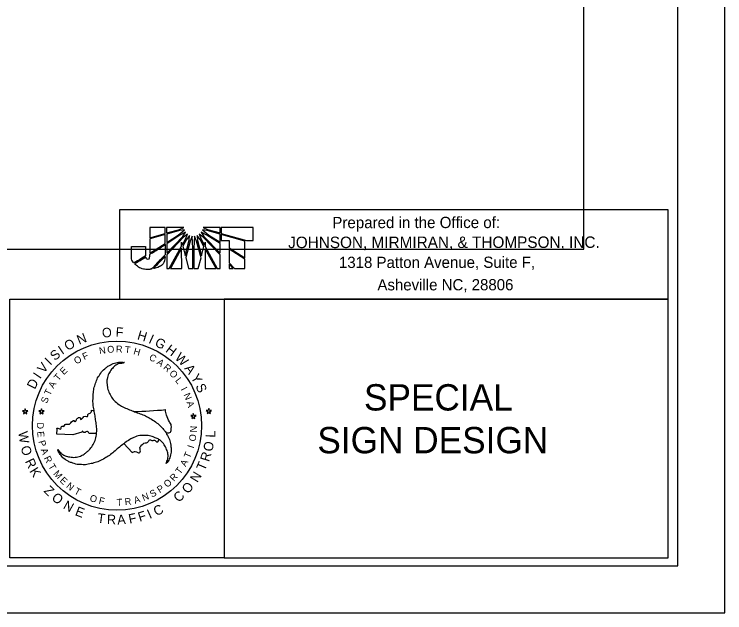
# Model space of a CAD drawing. Extents: x 766449 to 768137, y 650958 to 652521.
# Drawn here: x 767759.5 to 768137.3, y 651421.3 to 651739.5 of the extents above; entities that cross this region are included whole.
import ezdxf

# ---------------------------------------------------------------- set-up
doc = ezdxf.new("R2010")
doc.units = 0
for name, color, linetype in [('Default', 7, 'Continuous'), ('DEV BORDER CELL', 7, 'Continuous'), ('DEV DOT SWIRL SEAL CELL', 7, 'Continuous'), ('Scratch_Level_0', 7, 'Continuous'), ('Sheet Plan CELL', 7, 'Continuous'), ('Sheet Plot Border Outside CELL', 7, 'Continuous'), ('Sheet Title CELL', 7, 'Continuous'), ('Text', 7, 'Continuous')]:
    doc.layers.add(name, color=color, linetype=linetype)

msp = doc.modelspace()

# ---------------------------------------------------------------- linework, layer by layer
at = {"layer": 'Default'}
for p, q in [((767839.76, 651626.07), (767831.66, 651626.07)), ((767831.66, 651626.07), (767831.67, 651620.69)), ((767831.67, 651620.69), (767839.76, 651622.95)), ((767839.76, 651622.95), (767839.76, 651626.07)), ((767849.71, 651626.12), (767840.6, 651626.11)), ((767840.6, 651626.11), (767840.6, 651623.21)), ((767840.6, 651623.21), (767847.39, 651625.09)), ((767847.39, 651624.46), (767840.61, 651622.59)), ((767846.68, 651622.06), (767850.04, 651624.79)), ((767847.39, 651625.09), (767849.71, 651626.12)), ((767850.04, 651624.79), (767847.39, 651624.46)), ((767850.7, 651623.53), (767847.62, 651621.96)), ((767849.14, 651621.34), (767850.7, 651623.53)), ((767858.87, 651623.54), (767860.43, 651621.31)), ((767862, 651621.98), (767858.87, 651623.54)), ((767859.58, 651624.79), (767862.97, 651622.02)), ((767862.07, 651624.48), (767859.58, 651624.79)), ((767869.01, 651626.1), (767860.03, 651626.13)), ((767860.03, 651626.13), (767862.3, 651625.06)), ((767869.01, 651622.57), (767862.07, 651624.48)), ((767862.3, 651625.06), (767869.01, 651623.19)), ((767869.01, 651623.19), (767869.01, 651626.1)), ((767886.65, 651626.15), (767869.63, 651626.14)), ((767869.63, 651626.14), (767869.64, 651623.01)), ((767869.64, 651623.01), (767869.64, 651622.92)), ((767869.64, 651622.92), (767883.04, 651619.18)), ((767886.66, 651619.18), (767886.65, 651626.15)), ((767839.76, 651622.36), (767831.67, 651620.08)), ((767831.67, 651620.08), (767831.68, 651612.53)), ((767839.77, 651617.67), (767839.76, 651622.36)), ((767840.61, 651622.59), (767840.61, 651618.2)), ((767840.61, 651618.2), (767846.68, 651622.06)), ((767847.62, 651621.96), (767840.61, 651617.5)), ((767840.61, 651612.45), (767849.14, 651621.34)), ((767849.49, 651620.9), (767840.62, 651611.59)), ((767848.96, 651616.88), (767850.65, 651619.96)), ((767851.2, 651619.78), (767849.19, 651616.11)), ((767851.64, 651622.56), (767849.49, 651620.9)), ((767850.49, 651611.25), (767852.58, 651619.34)), ((767850.65, 651619.96), (767851.64, 651622.56)), ((767853.03, 651618.88), (767850.76, 651610.13)), ((767852.8, 651621.84), (767851.2, 651619.78)), ((767852.58, 651619.34), (767852.8, 651621.84)), ((767854.14, 651621.48), (767853.03, 651618.88)), ((767854.49, 651615.09), (767854.14, 651621.48)), ((767855.48, 651621.48), (767855.07, 651615.09)), ((767856.55, 651618.89), (767855.48, 651621.48)), ((767858.88, 651610), (767856.55, 651618.89)), ((767856.77, 651621.84), (767857.04, 651619.25)), ((767858.34, 651619.78), (767856.77, 651621.84)), ((767857.04, 651619.25), (767859.15, 651611.07)), ((767857.92, 651622.56), (767858.91, 651619.97)), ((767860.07, 651620.91), (767857.92, 651622.56)), ((767860.44, 651615.99), (767858.34, 651619.78)), ((767858.91, 651619.97), (767860.65, 651616.75)), ((767868.97, 651611.54), (767860.07, 651620.91)), ((767860.43, 651621.31), (767868.96, 651612.38)), ((767868.96, 651617.56), (767862, 651621.98)), ((767862.97, 651622.02), (767868.96, 651618.28)), ((767868.96, 651618.28), (767869.01, 651622.57)), ((767869.64, 651622.44), (767869.64, 651622.39)), ((767882.19, 651618.87), (767869.64, 651622.44)), ((767869.64, 651622.39), (767869.64, 651619.13)), ((767869.64, 651619.13), (767873.8, 651619.13)), ((767873.8, 651619.13), (767873.8, 651615.24)), ((767882.19, 651609.93), (767882.19, 651618.87)), ((767883.04, 651619.18), (767886.66, 651619.18)), ((767831.68, 651612.53), (767839.77, 651617.67)), ((767840.61, 651617.5), (767840.61, 651612.45)), ((767841.96, 651604.24), (767848.56, 651616.21)), ((767848.56, 651616.21), (767848.56, 651618.35)), ((767848.56, 651618.35), (767848.96, 651616.88)), ((767849.19, 651616.11), (767850.49, 651611.25)), ((767854.5, 651604.3), (767854.49, 651615.09)), ((767855.07, 651615.09), (767855.08, 651604.3)), ((767859.15, 651611.07), (767860.44, 651615.99)), ((767860.65, 651616.75), (767861.06, 651618.36)), ((767861.06, 651618.36), (767861.07, 651615.99)), ((767861.07, 651615.99), (767867.54, 651604.27)), ((767868.96, 651612.38), (767868.96, 651617.56)), ((767873.8, 651615.24), (767882.19, 651609.93)), ((767840.62, 651611.59), (767840.62, 651604.24)), ((767848.56, 651615.05), (767842.59, 651604.24)), ((767848.62, 651604.25), (767848.56, 651615.05)), ((767866.87, 651604.31), (767861.07, 651614.83)), ((767861.07, 651614.83), (767861.08, 651604.3)), ((767868.97, 651604.27), (767868.97, 651611.54)), ((767873.8, 651614.57), (767873.81, 651607.33)), ((767882.19, 651609.3), (767873.8, 651614.57)), ((767850.76, 651610.13), (767852.29, 651604.29)), ((767857.32, 651604.3), (767858.88, 651610)), ((767882.2, 651604.28), (767882.19, 651609.3)), ((767840.62, 651604.24), (767841.96, 651604.24)), ((767842.59, 651604.24), (767848.62, 651604.25)), ((767852.29, 651604.29), (767854.5, 651604.3)), ((767855.08, 651604.3), (767857.32, 651604.3)), ((767861.08, 651604.3), (767866.87, 651604.31)), ((767867.54, 651604.27), (767868.97, 651604.27)), ((767873.81, 651607.33), (767876.71, 651604.28)), ((767875.91, 651604.27), (767873.81, 651606.54)), ((767873.81, 651606.54), (767873.81, 651604.27)), ((767873.81, 651604.27), (767875.91, 651604.27)), ((767876.71, 651604.28), (767882.2, 651604.28))]:
    msp.add_line(p, q, dxfattribs=at)
for points in [[(767831.67, 651620.69), (767839.76, 651622.95), (767839.76, 651626.07), (767831.66, 651626.07), (767831.67, 651620.69)], [(767847.39, 651625.09), (767849.71, 651626.12), (767840.6, 651626.11), (767840.6, 651623.21), (767847.39, 651625.09)], [(767840.61, 651622.59), (767840.61, 651618.2), (767846.68, 651622.06), (767850.04, 651624.79), (767847.39, 651624.46), (767840.61, 651622.59)], [(767840.61, 651617.5), (767840.61, 651612.45), (767849.14, 651621.34), (767850.7, 651623.53), (767847.62, 651621.96), (767840.61, 651617.5)], [(767858.87, 651623.54), (767860.43, 651621.31), (767868.96, 651612.38), (767868.96, 651617.56), (767862, 651621.98), (767858.87, 651623.54)], [(767859.58, 651624.79), (767862.97, 651622.02), (767868.96, 651618.28), (767869.01, 651622.57), (767862.07, 651624.48), (767859.58, 651624.79)], [(767862.3, 651625.06), (767869.01, 651623.19), (767869.01, 651626.1), (767860.03, 651626.13), (767862.3, 651625.06)], [(767831.68, 651612.53), (767839.77, 651617.67), (767839.76, 651622.36), (767831.67, 651620.08), (767831.68, 651612.53)], [(767851.64, 651622.56), (767849.49, 651620.9), (767840.62, 651611.59), (767840.62, 651604.24), (767841.96, 651604.24), (767848.56, 651616.21), (767848.56, 651618.35), (767848.96, 651616.88), (767850.65, 651619.96), (767851.64, 651622.56)], [(767852.8, 651621.84), (767851.2, 651619.78), (767849.19, 651616.11), (767850.49, 651611.25), (767852.58, 651619.34), (767852.8, 651621.84)], [(767853.03, 651618.88), (767850.76, 651610.13), (767852.29, 651604.29), (767854.5, 651604.3), (767854.49, 651615.09), (767854.14, 651621.48), (767853.03, 651618.88)], [(767855.48, 651621.48), (767855.07, 651615.09), (767855.08, 651604.3), (767857.32, 651604.3), (767858.88, 651610), (767856.55, 651618.89), (767855.48, 651621.48)], [(767856.77, 651621.84), (767857.04, 651619.25), (767859.15, 651611.07), (767860.44, 651615.99), (767858.34, 651619.78), (767856.77, 651621.84)], [(767857.92, 651622.56), (767858.91, 651619.97), (767860.65, 651616.75), (767861.06, 651618.36), (767861.07, 651615.99), (767867.54, 651604.27), (767868.97, 651604.27), (767868.97, 651611.54), (767860.07, 651620.91), (767857.92, 651622.56)], [(767869.64, 651622.44), (767869.64, 651622.39), (767869.64, 651619.13), (767873.8, 651619.13), (767873.8, 651615.24), (767882.19, 651609.93), (767882.19, 651618.87), (767869.64, 651622.44)], [(767842.59, 651604.24), (767848.62, 651604.25), (767848.56, 651615.05), (767842.59, 651604.24)], [(767861.08, 651604.3), (767866.87, 651604.31), (767861.07, 651614.83), (767861.08, 651604.3)], [(767873.8, 651614.57), (767873.81, 651607.33), (767876.71, 651604.28), (767882.2, 651604.28), (767882.19, 651609.3), (767873.8, 651614.57), (767873.8, 651614.57)], [(767873.81, 651604.27), (767873.81, 651604.27), (767875.91, 651604.27), (767873.81, 651606.54), (767873.81, 651604.27)]]:
    msp.add_lwpolyline(points, dxfattribs=at)
for points in [[(767829.35, 651616), (767829.35, 651616), (767821.85, 651616), (767821.85, 651616), (767821.85, 651616), (767821.86, 651611.31), (767821.86, 651611.31), (767821.86, 651611.31), (767821.86, 651610.81), (767821.86, 651610.81), (767821.86, 651609.34), (767822.34, 651608.18), (767823.2, 651607.21), (767823.2, 651607.21), (767829.35, 651610.95), (767829.35, 651611.05), (767829.35, 651611.05), (767829.35, 651616), (767829.35, 651616)], [(767829.35, 651616), (767829.35, 651616), (767821.85, 651616), (767821.85, 651616), (767821.85, 651616), (767821.86, 651611.31), (767821.86, 651611.31), (767821.86, 651611.31), (767821.86, 651610.81), (767821.86, 651610.81), (767821.86, 651609.34), (767822.34, 651608.18), (767823.2, 651607.21), (767823.2, 651607.21), (767829.35, 651610.95), (767829.35, 651611.05), (767829.35, 651611.05), (767829.35, 651616), (767829.35, 651616)], [(767830.52, 651609.26), (767830.04, 651609.26), (767829.62, 651609.52), (767829.45, 651610.42), (767829.45, 651610.42), (767823.64, 651606.82), (767823.64, 651606.82), (767825.43, 651604.94), (767828.29, 651603.82), (767830.71, 651603.82), (767831.34, 651603.82), (767831.82, 651603.87), (767832.49, 651604.01), (767832.49, 651604.01), (767839.77, 651611.55), (767839.77, 651611.55), (767839.77, 651611.55), (767839.77, 651617), (767839.77, 651617), (767839.77, 651617), (767831.68, 651611.85), (767831.68, 651611.85), (767831.68, 651609.81), (767831.18, 651609.26), (767830.52, 651609.26)], [(767830.52, 651609.26), (767830.04, 651609.26), (767829.62, 651609.52), (767829.45, 651610.42), (767829.45, 651610.42), (767823.64, 651606.82), (767823.64, 651606.82), (767825.43, 651604.94), (767828.29, 651603.82), (767830.71, 651603.82), (767831.34, 651603.82), (767831.82, 651603.87), (767832.49, 651604.01), (767832.49, 651604.01), (767839.77, 651611.55), (767839.77, 651611.55), (767839.77, 651611.55), (767839.77, 651617), (767839.77, 651617), (767839.77, 651617), (767831.68, 651611.85), (767831.68, 651611.85), (767831.68, 651609.81), (767831.18, 651609.26), (767830.52, 651609.26)], [(767839.77, 651610.7), (767839.77, 651610.7), (767833.47, 651604.18), (767833.47, 651604.18), (767836.56, 651604.95), (767839.63, 651606.99), (767839.77, 651610.7)], [(767839.77, 651610.7), (767839.77, 651610.7), (767833.47, 651604.18), (767833.47, 651604.18), (767836.56, 651604.95), (767839.63, 651606.99), (767839.77, 651610.7)]]:
    msp.add_open_spline(points, degree=3, dxfattribs=at)
at = {"layer": 'DEV BORDER CELL'}
for points in [[(768112.34, 652496.28), (766612.34, 652496.28), (766612.34, 651446.28), (768112.34, 651446.28)], [(767757.19, 651588.05), (767871.19, 651588.05), (767871.19, 651450.55), (767757.19, 651450.55)], [(768107.19, 651588.05), (767871.19, 651588.05), (767871.19, 651450.55), (768107.19, 651450.55)]]:
    msp.add_lwpolyline(points, close=True, dxfattribs=at)
at = {"layer": 'DEV DOT SWIRL SEAL CELL'}
for p, q in [((767763.92, 651528.71), (767764.8, 651528.07)), ((767765, 651528.71), (767763.92, 651528.71)), ((767765.32, 651529.72), (767765, 651528.71)), ((767765.68, 651528.71), (767765.32, 651529.72)), ((767766.77, 651528.71), (767765.68, 651528.71)), ((767765.89, 651528.07), (767766.77, 651528.71)), ((767765.89, 651528.07), (767766.77, 651528.71)), ((767773.68, 651528.7), (767772.6, 651528.7)), ((767772.6, 651528.7), (767773.48, 651528.06)), ((767774, 651529.7), (767773.68, 651528.7)), ((767774.36, 651528.7), (767774, 651529.7)), ((767775.45, 651528.7), (767774.36, 651528.7)), ((767774.56, 651528.06), (767775.45, 651528.7)), ((767862.73, 651528.85), (767861.64, 651528.85)), ((767861.64, 651528.85), (767862.53, 651528.21)), ((767862.53, 651528.21), (767862.2, 651527.17)), ((767863.05, 651529.86), (767862.73, 651528.85)), ((767863.41, 651528.85), (767863.05, 651529.86)), ((767864.49, 651528.85), (767863.41, 651528.85)), ((767863.61, 651528.21), (767864.49, 651528.85)), ((767863.93, 651527.17), (767863.61, 651528.21)), ((767764.8, 651528.07), (767764.48, 651527.03)), ((767764.48, 651527.03), (767765.32, 651527.67)), ((767765.32, 651527.67), (767766.21, 651527.03)), ((767765.32, 651527.67), (767766.21, 651527.03)), ((767766.21, 651527.03), (767765.89, 651528.07)), ((767766.21, 651527.03), (767765.89, 651528.07)), ((767773.48, 651528.06), (767773.16, 651527.01)), ((767773.16, 651527.01), (767774, 651527.66)), ((767774, 651527.66), (767774.89, 651527.01)), ((767774.89, 651527.01), (767774.56, 651528.06)), ((767854.45, 651526.21), (767853.37, 651526.21)), ((767853.37, 651526.21), (767854.25, 651525.57)), ((767854.25, 651525.57), (767853.93, 651524.53)), ((767853.93, 651524.53), (767854.77, 651525.17)), ((767854.77, 651527.21), (767854.45, 651526.21)), ((767855.13, 651526.21), (767854.77, 651527.21)), ((767854.77, 651525.17), (767855.65, 651524.53)), ((767856.22, 651526.21), (767855.13, 651526.21)), ((767855.33, 651525.57), (767856.22, 651526.21)), ((767855.65, 651524.53), (767855.33, 651525.57)), ((767862.2, 651527.17), (767863.05, 651527.81)), ((767863.05, 651527.81), (767863.93, 651527.17)), ((767782.25, 651516.27), (767782.33, 651518.92)), ((767795.44, 651517.37), (767790.64, 651515.96)), ((767790.64, 651515.96), (767782.25, 651516.27)), ((767799.14, 651516.81), (767803.36, 651516.77)), ((767817.89, 651511.19), (767822.2, 651506.52))]:
    msp.add_line(p, q, dxfattribs=at)
for start, end in [(265.6785, 265.9762), (271.2035, 275.3236)]:
    msp.add_arc((767818.28, 651761.45), 233.19, start, end, dxfattribs=at)
for points in [[(767782.66, 651508.16), (767784.4, 651506.14), (767786.58, 651504.75), (767789.07, 651504.1), (767791.89, 651503.94), (767794.76, 651504.61), (767796.67, 651505.58), (767797.47, 651506.22), (767798.87, 651507.33), (767799.86, 651508.4), (767801.53, 651510.76), (767802.82, 651513.55), (767803.35, 651516.75), (767803.38, 651517.02), (767803.35, 651520.02), (767802.95, 651523.06), (767802.52, 651525.98), (767801.98, 651529.01), (767801.5, 651532.02), (767801.45, 651534.95), (767801.64, 651538.3), (767802.12, 651541.18), (767803.06, 651544.13), (767803.57, 651545.53), (767804.27, 651546.65), (767806.01, 651549.31), (767808.29, 651551.45), (767809.8, 651552.59), (767811.22, 651553.34), (767811.46, 651553.47), (767814.31, 651554.38), (767817.1, 651554.49), (767818.04, 651554.25)], [(767818.12, 651554.33), (767818.04, 651554.25), (767815.46, 651553.77), (767813.13, 651552.56), (767811.33, 651550.73), (767809.8, 651548.4), (767808.94, 651545.55), (767808.8, 651543.43), (767808.99, 651542.41), (767809.23, 651540.64), (767809.64, 651539.24), (767810.9, 651536.64), (767812.64, 651534.12), (767815.17, 651532.05), (767815.38, 651531.89), (767817.96, 651530.41), (767820.83, 651529.23), (767823.57, 651528.16), (767826.44, 651527.11), (767829.28, 651525.98), (767831.86, 651524.59), (767834.68, 651522.76), (767836.91, 651520.91), (767839, 651518.63), (767839.97, 651517.47), (767840.59, 651516.29), (767842.04, 651513.47), (767842.73, 651510.41), (767842.98, 651508.53), (767842.92, 651506.92), (767842.92, 651506.65), (767842.25, 651503.73), (767840.94, 651501.26), (767840.29, 651500.59)], [(767782.33, 651518.92), (767782.25, 651519.18), (767782.7, 651519.46), (767783.94, 651518.95), (767784.56, 651519.49), (767784.53, 651520.03), (767785.04, 651520.56), (767785.89, 651520.39), (767786.65, 651521.36), (767787.36, 651521.55), (767788.86, 651521.55), (767790.64, 651523.33), (767791.37, 651523.45), (767791.57, 651522.96), (767792.02, 651522.88), (767792.81, 651524.35), (767793.01, 651524.55), (767794.37, 651525.11), (767794.73, 651524.83), (767794.85, 651524.18), (767795.04, 651524.07), (767795.5, 651524.38), (767796.12, 651525.17), (767797.25, 651525.76), (767798.55, 651525.59), (767798.77, 651526.67), (767800.3, 651527.68), (767800.61, 651528.31), (767800.7, 651528.93)], [(767840.22, 651517.04), (767842.69, 651517.34), (767843.05, 651519.29), (767843.08, 651520.93), (767842.06, 651522.83), (767840.54, 651526.3), (767839.92, 651529.27)], [(767799.14, 651516.81), (767798.8, 651517.46), (767798.13, 651517.65), (767797.19, 651517.17), (767796.51, 651517.2), (767795.75, 651517.77), (767795.44, 651517.37)], [(767840.29, 651500.59), (767841.15, 651503.06), (767841.29, 651505.66), (767840.59, 651508.16), (767839.33, 651510.65), (767837.31, 651512.8), (767835.54, 651513.98), (767834.55, 651514.33), (767832.94, 651515.03), (767831.46, 651515.35), (767828.61, 651515.59), (767825.53, 651515.32), (767822.49, 651514.17), (767822.25, 651514.06), (767819.68, 651512.53), (767817.23, 651510.68), (767814.9, 651508.86), (767812.56, 651506.87), (767810.17, 651504.94), (767807.68, 651503.43), (767804.67, 651501.9), (767801.96, 651500.91), (767798.95, 651500.24), (767797.45, 651499.97), (767796.13, 651500.02), (767792.99, 651500.19), (767789.96, 651501.1), (767788.24, 651501.82), (767786.87, 651502.71), (767786.63, 651502.84), (767784.43, 651504.86), (767782.95, 651507.22), (767782.66, 651508.16)], [(767822.2, 651506.52), (767823.9, 651507.03), (767825.31, 651506.49), (767825.99, 651506.38), (767826.55, 651506.8), (767826.38, 651508.92), (767826.86, 651509.91), (767829.15, 651511.61), (767830.57, 651511.92), (767831.61, 651513.22), (767832.03, 651513.19), (767832.68, 651512.82), (767834.13, 651513.11), (767835.28, 651512.17), (767835.96, 651512.23), (767836.5, 651513.29)]]:
    msp.add_spline(points, degree=3, dxfattribs=at)
at = {"layer": 'Scratch_Level_0'}
msp.add_lwpolyline([(768062.34, 652446.28), (766662.34, 652446.28), (766662.34, 651496.28), (767541.19, 651496.28), (767541.19, 651614.55), (768062.34, 651614.55)], close=True, dxfattribs=at)
at = {"layer": 'Sheet Plan CELL'}
msp.add_lwpolyline([(768107.19, 651635.57), (767815.52, 651635.57), (767815.52, 651588.05), (768107.19, 651588.05)], close=True, dxfattribs=at)
at = {"layer": 'Sheet Plot Border Outside CELL'}
msp.add_lwpolyline([(766449.34, 651421.28), (768137.34, 651421.28), (768137.34, 652521.28), (766449.34, 652521.28)], close=True, dxfattribs=at)
at = {"layer": 'Text'}
msp.add_circle((767814.19, 651520.76), 44.97, dxfattribs=at)

# ---------------------------------------------------------------- texts
at = {"layer": 'Default'}
for s, p in [('SPECIAL', (767945.51, 651528.81)), ('SIGN DESIGN', (767920.72, 651506.06))]:
    msp.add_text(s, height=14, dxfattribs=at).set_placement(p)
at = {"layer": 'DEV DOT SWIRL SEAL CELL'}
for s, height, rotation, p in [('N', 5.04, 21.5861, (767794.05, 651563.75)), ('O', 5.04, 5.7649, (767806.45, 651567.49)), ('F', 5.04, 357.2575, (767813.4, 651568.04)), ('H', 5.04, 343.454, (767824.63, 651566.75)), ('O', 5.04, 30.0935, (767787.94, 651560.38)), ('I', 5.04, 335.804, (767830.63, 651564.88)), ('G', 5.04, 331.5167, (767833.86, 651563.49)), ('I', 5.04, 34.3808, (767785.06, 651558.35)), ('N', 3.63, 9.0227, (767804.97, 651558.7)), ('O', 3.63, 3.9446, (767809.11, 651559.42)), ('R', 3.63, 358.8665, (767813.59, 651559.69)), ('H', 3.63, 343.6322, (767822.67, 651558.83)), ('H', 5.04, 323.4632, (767839.61, 651560.24)), ('S', 5.04, 40.5848, (767781.2, 651555.04)), ('F', 3.63, 24.2569, (767796.75, 651555.58)), ('C', 3.63, 333.4761, (767830.9, 651555.91)), ('W', 5.04, 315.8133, (767844.61, 651556.44)), ('V', 5.04, 51.5806, (767775.3, 651548.22)), ('I', 5.04, 44.8722, (767778.74, 651552.51)), ('O', 3.63, 29.335, (767792.54, 651553.23)), ('A', 3.63, 323.3199, (767835, 651553.79)), ('E', 3.63, 44.5692, (767785.93, 651547.55)), ('R', 3.63, 318.2418, (767838.49, 651551.23)), ('A', 5.04, 306.7762, (767849.79, 651551.14)), ('I', 5.04, 55.8679, (767773.37, 651545.27)), ('T', 3.63, 49.6473, (767783.07, 651544.24)), ('O', 3.63, 313.1637, (767841.7, 651548.32)), ('Y', 5.04, 299.7484, (767853.21, 651546.49)), ('D', 5.04, 63.459, (767770.52, 651539.74)), ('A', 3.63, 59.8035, (767780.51, 651540.25)), ('L', 3.63, 308.0856, (767844.92, 651544.64)), ('T', 3.63, 64.8816, (767778.57, 651536.46)), ('I', 3.63, 297.9295, (767847.96, 651540.14)), ('S', 5.04, 293.2249, (767855.85, 651541.84)), ('S', 3.63, 69.9597, (767776.98, 651532.32)), ('N', 3.63, 292.8514, (767849.48, 651537.23)), ('A', 3.63, 287.7733, (767851.08, 651533.18)), ('D', 3.63, 270.272, (767771.64, 651522.46)), ('E', 3.63, 275.3501, (767771.75, 651517.6)), ('N', 3.63, 87.733, (767856.63, 651517.1)), ('O', 3.63, 82.9269, (767856, 651512.23)), ('P', 3.63, 285.5063, (767772.36, 651512.39)), ('I', 3.63, 72.7707, (767854.92, 651508.47)), ('A', 3.63, 290.5843, (767773.56, 651507.93)), ('T', 3.63, 67.6926, (767852.93, 651503.08)), ('R', 3.63, 295.6624, (767775.23, 651503.6)), ('A', 3.63, 62.6145, (767850.7, 651498.74)), ('T', 3.63, 300.7405, (767777.51, 651499.19)), ('T', 3.63, 52.4584, (767847.75, 651494.6)), ('M', 3.63, 310.8967, (767780.13, 651495.1)), ('R', 3.63, 47.3803, (767844.49, 651490.85)), ('E', 3.63, 315.9748, (767783.47, 651491.28)), ('N', 3.63, 321.0529, (767786.89, 651488.12)), ('O', 3.63, 42.3022, (767840.96, 651487.59)), ('T', 3.63, 331.209, (767791.13, 651484.88)), ('S', 3.63, 27.068, (767832.76, 651482.46)), ('P', 3.63, 32.146, (767836.89, 651484.77)), ('O', 3.63, 341.3652, (767799.34, 651480.86)), ('A', 3.63, 16.9118, (767823.77, 651479.2)), ('N', 3.63, 21.9899, (767828.35, 651480.59)), ('F', 3.63, 346.4433, (767804.26, 651479.38)), ('T', 3.63, 1.6775, (767814.02, 651478.19)), ('R', 3.63, 6.7556, (767818.51, 651478.43))]:
    msp.add_text(s, height=height, rotation=rotation, dxfattribs=at).set_placement(p)
at = {"layer": 'Sheet Title CELL'}
for s, height, p in [('Prepared in the Office of:', 5.9987, (767928.69, 651625.72)), ('JOHNSON, MIRMIRAN, & THOMPSON, INC.', 6.0929, (767905.17, 651615.12)), ('1318 Patton Avenue, Suite F,', 5.9679, (767932.21, 651604.57)), ('Asheville NC, 28806', 5.9679, (767952.66, 651592.65))]:
    msp.add_text(s, height=height, rotation=0.0516, dxfattribs=at).set_placement(p)
at = {"layer": 'Text'}
for s, height, rotation, p in [('T', 3.63, 353.7884, (767818.22, 651559.47)), ('W', 5.04, 278.15, (767761.71, 651517.38)), ('L', 5.04, 87.429, (767866.39, 651514.31)), ('O', 5.04, 287.1147, (767762.87, 651509.25)), ('O', 5.04, 78.9896, (767864.88, 651506.72)), ('R', 5.04, 72.7519, (767863.05, 651501.29)), ('R', 5.04, 295.5541, (767765.12, 651501.84)), ('T', 5.04, 66.881, (767860.8, 651496.4)), ('K', 5.04, 301.7918, (767767.46, 651496.62)), ('N', 5.04, 58.892, (767856.97, 651490.15)), ('O', 5.04, 50.4526, (767852.01, 651484.21)), ('Z', 5.04, 316.1688, (767774.92, 651485.77)), ('O', 5.04, 322.5233, (767779.03, 651481.64)), ('C', 5.04, 43.0807, (767847.01, 651479.66)), ('N', 5.04, 330.9626, (767785.15, 651476.9)), ('E', 5.04, 338.9517, (767791.53, 651473.29)), ('F', 5.04, 17.7627, (767826.28, 651469.57)), ('I', 5.04, 23.7503, (767831.55, 651471.11)), ('C', 5.04, 28.0033, (767835.19, 651472.53)), ('T', 5.04, 352.6948, (767803.46, 651469.27)), ('R', 5.04, 358.5656, (767808.78, 651468.44)), ('A', 5.04, 4.8034, (767814.49, 651468.16)), ('F', 5.04, 11.7751, (767820.88, 651468.59))]:
    msp.add_text(s, height=height, rotation=rotation, dxfattribs=at).set_placement(p)

doc.saveas('drawing.dxf')
